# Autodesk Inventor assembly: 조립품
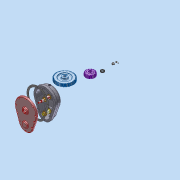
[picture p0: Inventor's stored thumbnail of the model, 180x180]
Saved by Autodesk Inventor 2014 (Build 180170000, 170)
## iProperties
Created: 2024-05
Part Number: 조립품
Document SubType Name: Assembly
Designer: dg
Author: dg
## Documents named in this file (13)
- C:\Users\dg\Desktop\740504V1002\조립품.iam
- C:\Users\dg\Desktop\740504V1002\본체.ipt
- C:\Users\dg\Desktop\740504V1002\가져온 구성요소\상단 축\상단 축.ipt
- C:\Users\dg\Desktop\740504V1002\가져온 구성요소\가스켓\가스켓.ipt
- C:\Users\dg\Desktop\740504V1002\가져온 구성요소\스퍼기어A\스퍼기어A.ipt
- C:\Users\dg\Desktop\740504V1002\가져온 구성요소\스퍼기어B\스퍼기어B.ipt
- C:\Users\dg\Desktop\740504V1002\가져온 구성요소\오일 실 10 20 4\오일 실 10 20 4.ipt
- C:\Users\dg\Desktop\740504V1002\가져온 구성요소\오일리스 부시\오일리스 부시.ipt
- C:\Users\dg\Desktop\740504V1002\가져온 구성요소\육각 머리 볼트  M6x0.75x6\육각 머리 볼트  M6x0.75x6.ipt
- C:\Users\dg\Desktop\740504V1002\가져온 구성요소\육각 소켓 머리 볼트 M4x10\육각 소켓 머리 볼트 M4x10.ipt
- C:\Users\dg\Desktop\740504V1002\가져온 구성요소\커버\커버.ipt
- C:\Users\dg\Desktop\740504V1002\가져온 구성요소\평행키 5x5x12\평행키 5x5x12.ipt
- C:\Users\dg\Desktop\740504V1002\가져온 구성요소\하단 축\하단 축.ipt
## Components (2 placed, 2 different names)
1. 가스켓:1
2. 하단 축:1
